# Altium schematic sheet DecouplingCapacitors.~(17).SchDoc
size A4
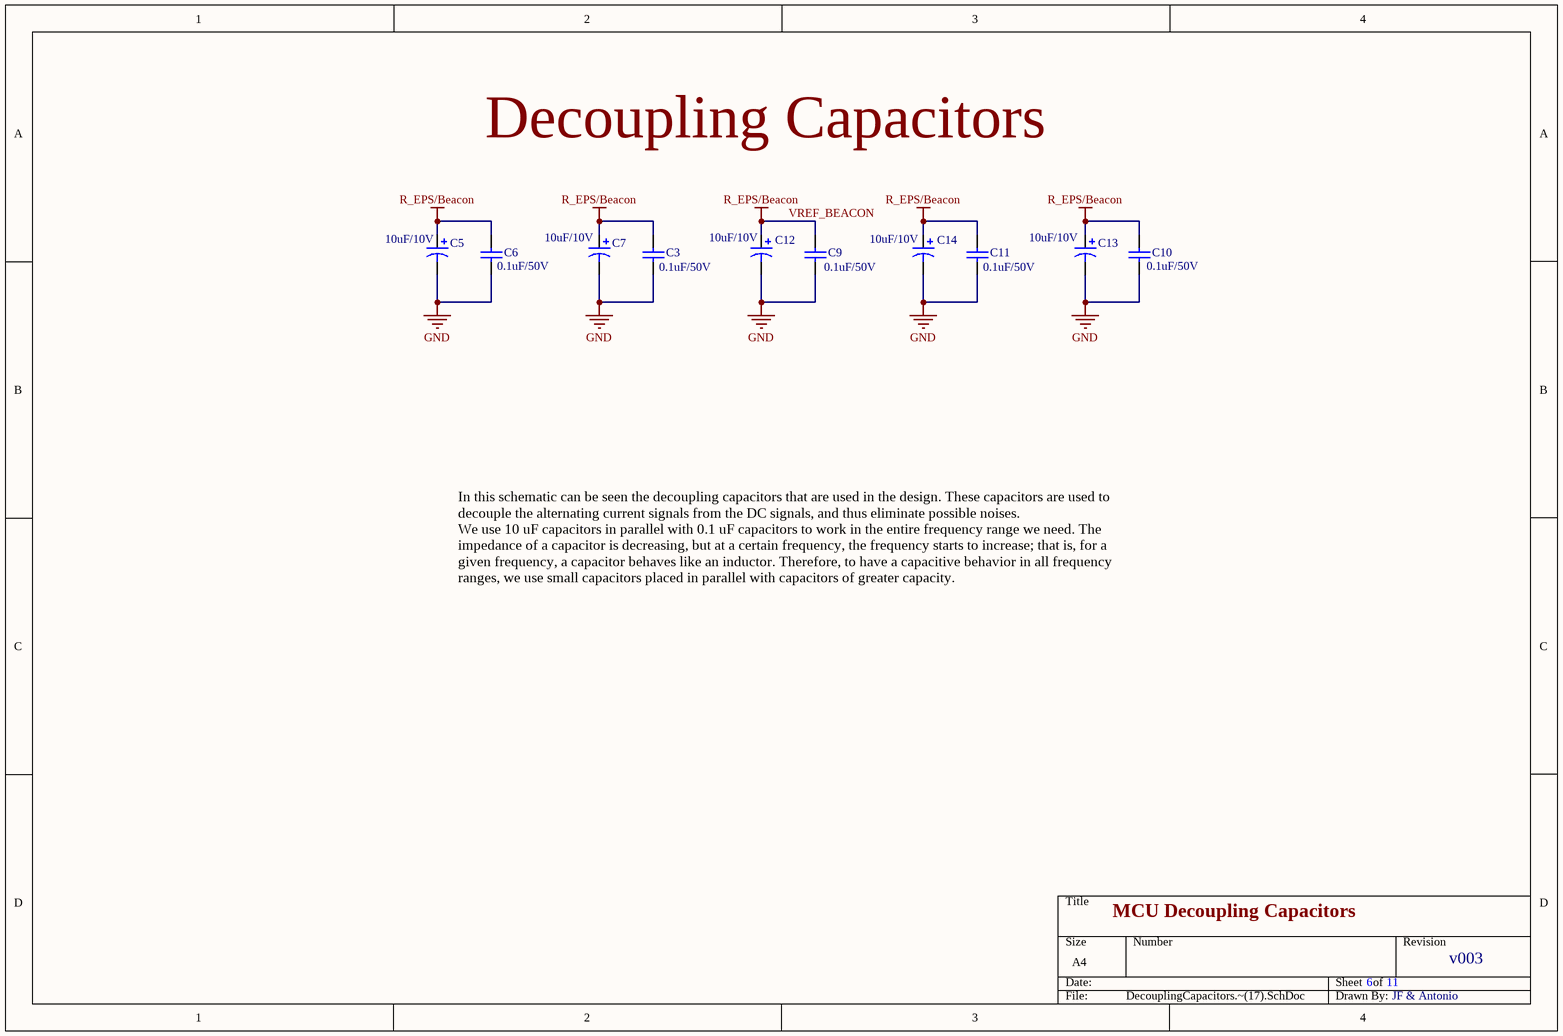
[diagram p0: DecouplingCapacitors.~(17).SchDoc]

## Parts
C3  value 0.1uF/50V  [CN]
C5  value 10uF/10V  [C10u]
C6  value 0.1uF/50V  [CN]
C7  value 10uF/10V  [C10u]
C9  value 0.1uF/50V  [CN]
C10  value 0.1uF/50V  [CN]
C11  value 0.1uF/50V  [CN]
C12  value 10uF/10V  [C10u]
C13  value 10uF/10V  [C10u]
C14  value 10uF/10V  [C10u]

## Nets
GND: C3.2 C5.2 C6.2 C7.2 C9.2 C10.2 C11.2 C12.2 C13.2 C14.2
VREF_BEACON: C3.1 C5.1 C6.1 C7.1 C9.1 C10.1 C11.1 C12.1 C13.1 C14.1  [also labelled R_EPS/Beacon]

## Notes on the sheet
- Decoupling Capacitors
- In this schematic can be seen the decoupling capacitors that are used in the design. These capacitors are used to decouple the alternating current signals from the DC signals, and thus eliminate possible noises.
  We use 10 uF capacitors in parallel with 0.1 uF capacitors to work in the entire frequency range we need. The impedance of a capacitor is decreasing, but at a certain frequency, the frequency starts to increase; that is, for a given frequency, a capacitor behaves like an inductor. Therefore, to have a capacitive behavior in all frequency ranges, we use small capacitors placed in parallel with capacitors of greater capacity.
- MCU Decoupling Capacitors
- 6
- 11
- v003
- JF & Antonio

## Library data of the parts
C3 C6 C9-C11 = Cap Semi: Capacitor (Semiconductor SIM Model)
C5 C7 C12-C14 = Cap Pol3: Polarized Capacitor (Surface Mount)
